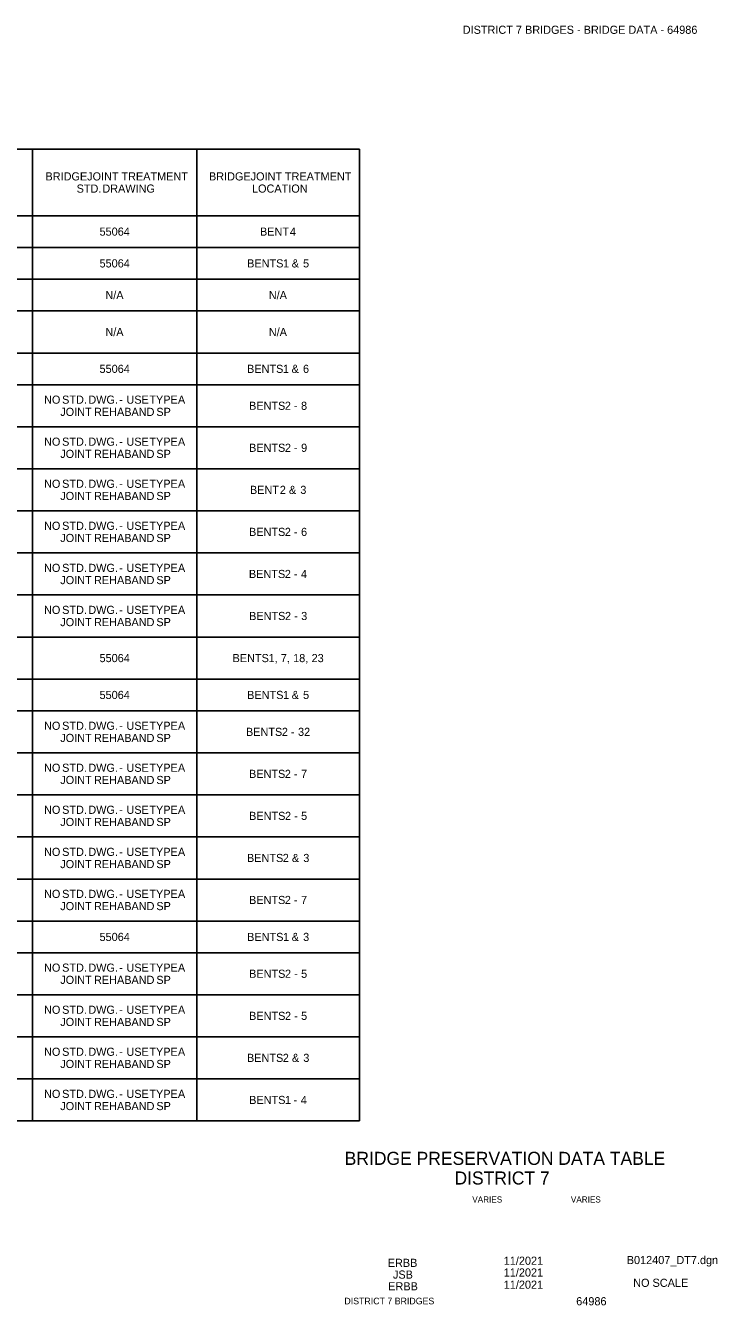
# Model space of a CAD drawing. Extents: x 16 to 1228740, y 11 to 152440.
# Drawn here: x 17.546 to 18.43, y 10.769 to 12.405 of the extents above; entities that cross this region are included whole.
import ezdxf

# ---------------------------------------------------------------- set-up
doc = ezdxf.new("R2010")
doc.units = 0
doc.layers.add('B_Concrete hidden', color=7, linetype='Continuous')
doc.layers.add('Default', color=7, linetype='Continuous')

msp = doc.modelspace()

# ---------------------------------------------------------------- linework, layer by layer
at = {"layer": 'Default'}
for p, q in [((16.2529, 12.2472), (17.9726, 12.2472)), ((17.5548, 11.0051), (17.5548, 12.2472)), ((17.7647, 11.0051), (17.7647, 12.2472)), ((17.9726, 11.0051), (17.9726, 12.2472)), ((16.2529, 12.1621), (17.9726, 12.1621)), ((16.2529, 12.1215), (17.9726, 12.1215)), ((16.2529, 12.0809), (17.9726, 12.0809)), ((16.2529, 12.0404), (17.9726, 12.0404)), ((16.2529, 11.9866), (17.9726, 11.9866)), ((16.2529, 11.9461), (17.9726, 11.9461)), ((16.2529, 11.8923), (17.9726, 11.8923)), ((16.2529, 11.8386), (17.9726, 11.8386)), ((16.2529, 11.7848), (17.9726, 11.7848)), ((16.2529, 11.7311), (17.9726, 11.7311)), ((16.2529, 11.6774), (17.9726, 11.6774)), ((16.2529, 11.6236), (17.9726, 11.6236)), ((16.2529, 11.5699), (17.9726, 11.5699)), ((16.2529, 11.5293), (17.9726, 11.5293)), ((16.2529, 11.4756), (17.9726, 11.4756)), ((16.2529, 11.4218), (17.9726, 11.4218)), ((16.2529, 11.3681), (17.9726, 11.3681)), ((16.2529, 11.3143), (17.9726, 11.3143)), ((16.2529, 11.2606), (17.9726, 11.2606)), ((16.2529, 11.22), (17.9726, 11.22)), ((16.2529, 11.1663), (17.9726, 11.1663)), ((16.2529, 11.1126), (17.9726, 11.1126)), ((16.2529, 11.0588), (17.9726, 11.0588)), ((16.2529, 11.0051), (17.9726, 11.0051))]:
    msp.add_line(p, q, dxfattribs=at)

# ---------------------------------------------------------------- texts
at = {"layer": 'B_Concrete hidden'}
for s, height, p in [('DISTRICT 7 BRIDGES - BRIDGE DATA - 64986', 0.0104, (18.1046, 12.3946)), ('BRIDGE PRESERVATION DATA TABLE', 0.0167, (17.9538, 10.9489)), ('DISTRICT 7', 0.0167, (18.0941, 10.9238)), ('VARIES', 0.0078, (18.1168, 10.9008)), ('VARIES', 0.0078, (18.2428, 10.9008)), ('11/2021', 0.0104, (18.157, 10.8212)), ('B012407_DT7.dgn', 0.0104, (18.3142, 10.8221)), ('ERBB', 0.0104, (18.0088, 10.8185)), ('JSB', 0.0104, (18.0154, 10.8035)), ('11/2021', 0.0104, (18.157, 10.8062)), ('ERBB', 0.0104, (18.0094, 10.7885)), ('11/2021', 0.0104, (18.157, 10.7906)), ('NO SCALE', 0.0104, (18.3224, 10.793)), ('DISTRICT 7 BRIDGES', 0.0084, (17.9534, 10.7707)), ('64986', 0.01042, (18.2496, 10.7694))]:
    msp.add_text(s, height=height, dxfattribs=at).set_placement(p)
at = {"layer": 'Default'}
for s, p in [('BRIDGE', (17.5714, 12.2072)), (' JOINT', (17.6208, 12.2072)), (' TREATMENT', (17.6646, 12.2072)), ('BRIDGE', (17.7803, 12.2072)), (' JOINT', (17.8297, 12.2072)), (' TREATMENT', (17.8735, 12.2072)), ('STD.', (17.6112, 12.1916)), (' DRAWING', (17.6402, 12.1916)), ('LOCATION', (17.8353, 12.1916)), ('55064', (17.6405, 12.1366)), ('BENT', (17.8455, 12.1366)), (' 4', (17.8799, 12.1366)), ('55064', (17.6405, 12.096)), ('BENTS', (17.8291, 12.096)), (' 1', (17.8711, 12.096)), (' &', (17.8822, 12.096)), (' 5', (17.8967, 12.096)), ('N/A', (17.648, 12.0555)), ('N/A', (17.8568, 12.0555)), ('N/A', (17.648, 12.0083)), ('N/A', (17.8568, 12.0083)), ('55064', (17.6405, 11.9612)), ('BENTS', (17.829, 11.9612)), (' 1', (17.8709, 11.9612)), (' &', (17.882, 11.9612)), (' 6', (17.8966, 11.9612)), ('NO', (17.5696, 11.9218)), (' STD.', (17.5888, 11.9218)), (' DWG.', (17.6223, 11.9218)), (' -', (17.6619, 11.9218)), (' USE', (17.671, 11.9218)), (' TYPE', (17.7003, 11.9218)), (' A', (17.7368, 11.9218)), ('JOINT', (17.5903, 11.9062)), (' REHAB', (17.6296, 11.9062)), (' AND', (17.6774, 11.9062)), (' SP', (17.7092, 11.9062)), ('BENTS', (17.8315, 11.914)), (' 2', (17.8734, 11.914)), (' -', (17.8851, 11.914)), (' 8', (17.8941, 11.914)), ('NO', (17.5696, 11.8681)), (' STD.', (17.5888, 11.8681)), (' DWG.', (17.6223, 11.8681)), (' USE', (17.671, 11.8681)), (' TYPE', (17.7003, 11.8681)), (' A', (17.7368, 11.8681)), ('JOINT', (17.5903, 11.8525)), (' REHAB', (17.6296, 11.8525)), (' -', (17.6619, 11.8681)), (' AND', (17.6774, 11.8525)), (' SP', (17.7092, 11.8525)), ('BENTS', (17.8315, 11.8603)), (' 2', (17.8735, 11.8603)), (' -', (17.8851, 11.8603)), (' 9', (17.8942, 11.8603)), ('NO', (17.5696, 11.8143)), (' STD.', (17.5888, 11.8143)), (' DWG.', (17.6223, 11.8143)), (' -', (17.6619, 11.8143)), (' USE', (17.671, 11.8143)), (' TYPE', (17.7003, 11.8143)), (' A', (17.7368, 11.8143)), ('BENT', (17.8327, 11.8065)), (' 2', (17.867, 11.8065)), (' &', (17.8787, 11.8065)), (' 3', (17.8932, 11.8065)), ('JOINT', (17.5903, 11.7987)), (' REHAB', (17.6296, 11.7987)), (' AND', (17.6774, 11.7987)), (' SP', (17.7092, 11.7987)), ('NO', (17.5696, 11.7606)), (' STD.', (17.5888, 11.7606)), (' DWG.', (17.6223, 11.7606)), (' -', (17.6619, 11.7606)), (' USE', (17.671, 11.7606)), (' TYPE', (17.7003, 11.7606)), (' A', (17.7368, 11.7606)), ('BENTS', (17.8315, 11.7528)), (' 2', (17.8734, 11.7528)), (' 6', (17.8941, 11.7528)), ('JOINT', (17.5903, 11.745)), (' REHAB', (17.6296, 11.745)), (' AND', (17.6774, 11.745)), (' SP', (17.7092, 11.745)), (' -', (17.8851, 11.7528)), ('NO', (17.5696, 11.7068)), (' STD.', (17.5888, 11.7068)), (' DWG.', (17.6223, 11.7068)), (' USE', (17.671, 11.7068)), (' TYPE', (17.7003, 11.7068)), (' A', (17.7368, 11.7068)), ('JOINT', (17.5903, 11.6912)), (' REHAB', (17.6296, 11.6912)), (' -', (17.6619, 11.7068)), (' AND', (17.6774, 11.6912)), (' SP', (17.7092, 11.6912)), ('BENTS', (17.8314, 11.699)), (' 2', (17.8734, 11.699)), (' -', (17.885, 11.699)), (' 4', (17.894, 11.699)), ('NO', (17.5696, 11.6531)), (' STD.', (17.5888, 11.6531)), (' DWG.', (17.6223, 11.6531)), (' USE', (17.671, 11.6531)), ('JOINT', (17.5903, 11.6375)), (' REHAB', (17.6296, 11.6375)), (' -', (17.6619, 11.6531)), (' AND', (17.6774, 11.6375)), (' TYPE', (17.7003, 11.6531)), (' SP', (17.7092, 11.6375)), (' A', (17.7368, 11.6531)), ('BENTS', (17.8316, 11.6453)), (' 2', (17.8736, 11.6453)), (' -', (17.8852, 11.6453)), (' 3', (17.8943, 11.6453)), ('55064', (17.6405, 11.5915)), ('BENTS', (17.8105, 11.5915)), (' 1,', (17.8525, 11.5915)), (' 7,', (17.8682, 11.5915)), (' 18,', (17.884, 11.5915)), (' 23', (17.9076, 11.5915)), ('55064', (17.6405, 11.5444)), ('BENTS', (17.8291, 11.5444)), (' 1', (17.8711, 11.5444)), (' &', (17.8822, 11.5444)), (' 5', (17.8967, 11.5444)), ('NO', (17.5696, 11.505)), ('JOINT', (17.5903, 11.4894)), (' STD.', (17.5888, 11.505)), (' DWG.', (17.6223, 11.505)), (' -', (17.6619, 11.505)), (' USE', (17.671, 11.505)), (' TYPE', (17.7003, 11.505)), (' SP', (17.7092, 11.4894)), (' A', (17.7368, 11.505)), ('BENTS', (17.8276, 11.4972)), (' 2', (17.8696, 11.4972)), (' -', (17.8812, 11.4972)), (' 32', (17.8903, 11.4972)), (' REHAB', (17.6296, 11.4894)), (' AND', (17.6774, 11.4894)), ('NO', (17.5696, 11.4513)), (' STD.', (17.5888, 11.4513)), (' DWG.', (17.6223, 11.4513)), (' -', (17.6619, 11.4513)), (' USE', (17.671, 11.4513)), (' TYPE', (17.7003, 11.4513)), (' A', (17.7368, 11.4513)), ('BENTS', (17.8315, 11.4435)), (' 2', (17.8734, 11.4435)), (' 7', (17.8941, 11.4435)), ('JOINT', (17.5903, 11.4357)), (' REHAB', (17.6296, 11.4357)), (' AND', (17.6774, 11.4357)), (' SP', (17.7092, 11.4357)), (' -', (17.8851, 11.4435)), ('NO', (17.5696, 11.3976)), (' STD.', (17.5888, 11.3976)), (' DWG.', (17.6223, 11.3976)), (' -', (17.6619, 11.3976)), (' USE', (17.671, 11.3976)), (' TYPE', (17.7003, 11.3976)), (' A', (17.7368, 11.3976)), ('JOINT', (17.5903, 11.382)), (' REHAB', (17.6296, 11.382)), (' AND', (17.6774, 11.382)), (' SP', (17.7092, 11.382)), ('BENTS', (17.8316, 11.3898)), (' 2', (17.8736, 11.3898)), (' -', (17.8852, 11.3898)), (' 5', (17.8942, 11.3898)), ('NO', (17.5696, 11.3438)), (' STD.', (17.5888, 11.3438)), (' DWG.', (17.6223, 11.3438)), (' USE', (17.671, 11.3438)), (' TYPE', (17.7003, 11.3438)), (' A', (17.7368, 11.3438)), ('JOINT', (17.5903, 11.3282)), (' REHAB', (17.6296, 11.3282)), (' -', (17.6619, 11.3438)), (' AND', (17.6774, 11.3282)), (' SP', (17.7092, 11.3282)), ('BENTS', (17.8289, 11.336)), (' 2', (17.8708, 11.336)), (' &', (17.8825, 11.336)), (' 3', (17.897, 11.336)), ('NO', (17.5696, 11.2901)), (' STD.', (17.5888, 11.2901)), (' DWG.', (17.6223, 11.2901)), (' -', (17.6619, 11.2901)), (' USE', (17.671, 11.2901)), (' TYPE', (17.7003, 11.2901)), (' A', (17.7368, 11.2901)), ('BENTS', (17.8315, 11.2823)), (' 2', (17.8734, 11.2823)), (' 7', (17.8941, 11.2823)), ('JOINT', (17.5903, 11.2745)), (' REHAB', (17.6296, 11.2745)), (' AND', (17.6774, 11.2745)), (' SP', (17.7092, 11.2745)), (' -', (17.8851, 11.2823)), ('55064', (17.6405, 11.2351)), ('BENTS', (17.8291, 11.2351)), (' 1', (17.8711, 11.2351)), (' &', (17.8822, 11.2351)), (' 3', (17.8968, 11.2351)), ('NO', (17.5696, 11.1958)), (' STD.', (17.5888, 11.1958)), (' DWG.', (17.6223, 11.1958)), (' USE', (17.671, 11.1958)), (' TYPE', (17.7003, 11.1958)), (' A', (17.7368, 11.1958)), ('JOINT', (17.5903, 11.1802)), (' REHAB', (17.6296, 11.1802)), (' -', (17.6619, 11.1958)), (' AND', (17.6774, 11.1802)), (' SP', (17.7092, 11.1802)), ('BENTS', (17.8316, 11.188)), (' 2', (17.8736, 11.188)), (' -', (17.8852, 11.188)), (' 5', (17.8942, 11.188)), ('NO', (17.5696, 11.142)), (' STD.', (17.5888, 11.142)), (' DWG.', (17.6223, 11.142)), (' -', (17.6619, 11.142)), (' USE', (17.671, 11.142)), (' TYPE', (17.7003, 11.142)), (' A', (17.7368, 11.142)), ('BENTS', (17.8316, 11.1342)), (' 2', (17.8736, 11.1342)), (' 5', (17.8942, 11.1342)), ('JOINT', (17.5903, 11.1264)), (' REHAB', (17.6296, 11.1264)), (' AND', (17.6774, 11.1264)), (' SP', (17.7092, 11.1264)), (' -', (17.8852, 11.1342)), ('NO', (17.5696, 11.0883)), (' STD.', (17.5888, 11.0883)), (' DWG.', (17.6223, 11.0883)), (' -', (17.6619, 11.0883)), (' USE', (17.671, 11.0883)), (' TYPE', (17.7003, 11.0883)), (' A', (17.7368, 11.0883)), ('BENTS', (17.8289, 11.0805)), (' 2', (17.8708, 11.0805)), (' 3', (17.897, 11.0805)), ('JOINT', (17.5903, 11.0727)), (' REHAB', (17.6296, 11.0727)), (' AND', (17.6774, 11.0727)), (' SP', (17.7092, 11.0727)), (' &', (17.8825, 11.0805)), ('NO', (17.5696, 11.0345)), (' STD.', (17.5888, 11.0345)), (' DWG.', (17.6223, 11.0345)), (' USE', (17.671, 11.0345)), (' TYPE', (17.7003, 11.0345)), (' A', (17.7368, 11.0345)), ('JOINT', (17.5903, 11.0189)), (' REHAB', (17.6296, 11.0189)), (' -', (17.6619, 11.0345)), (' AND', (17.6774, 11.0189)), (' SP', (17.7092, 11.0189)), ('BENTS', (17.8317, 11.0267)), (' 1', (17.8736, 11.0267)), (' -', (17.8847, 11.0267)), (' 4', (17.8938, 11.0267))]:
    msp.add_text(s, height=0.0104, dxfattribs=at).set_placement(p)

doc.saveas('drawing.dxf')
